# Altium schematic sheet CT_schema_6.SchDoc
size 369 x 245 mm
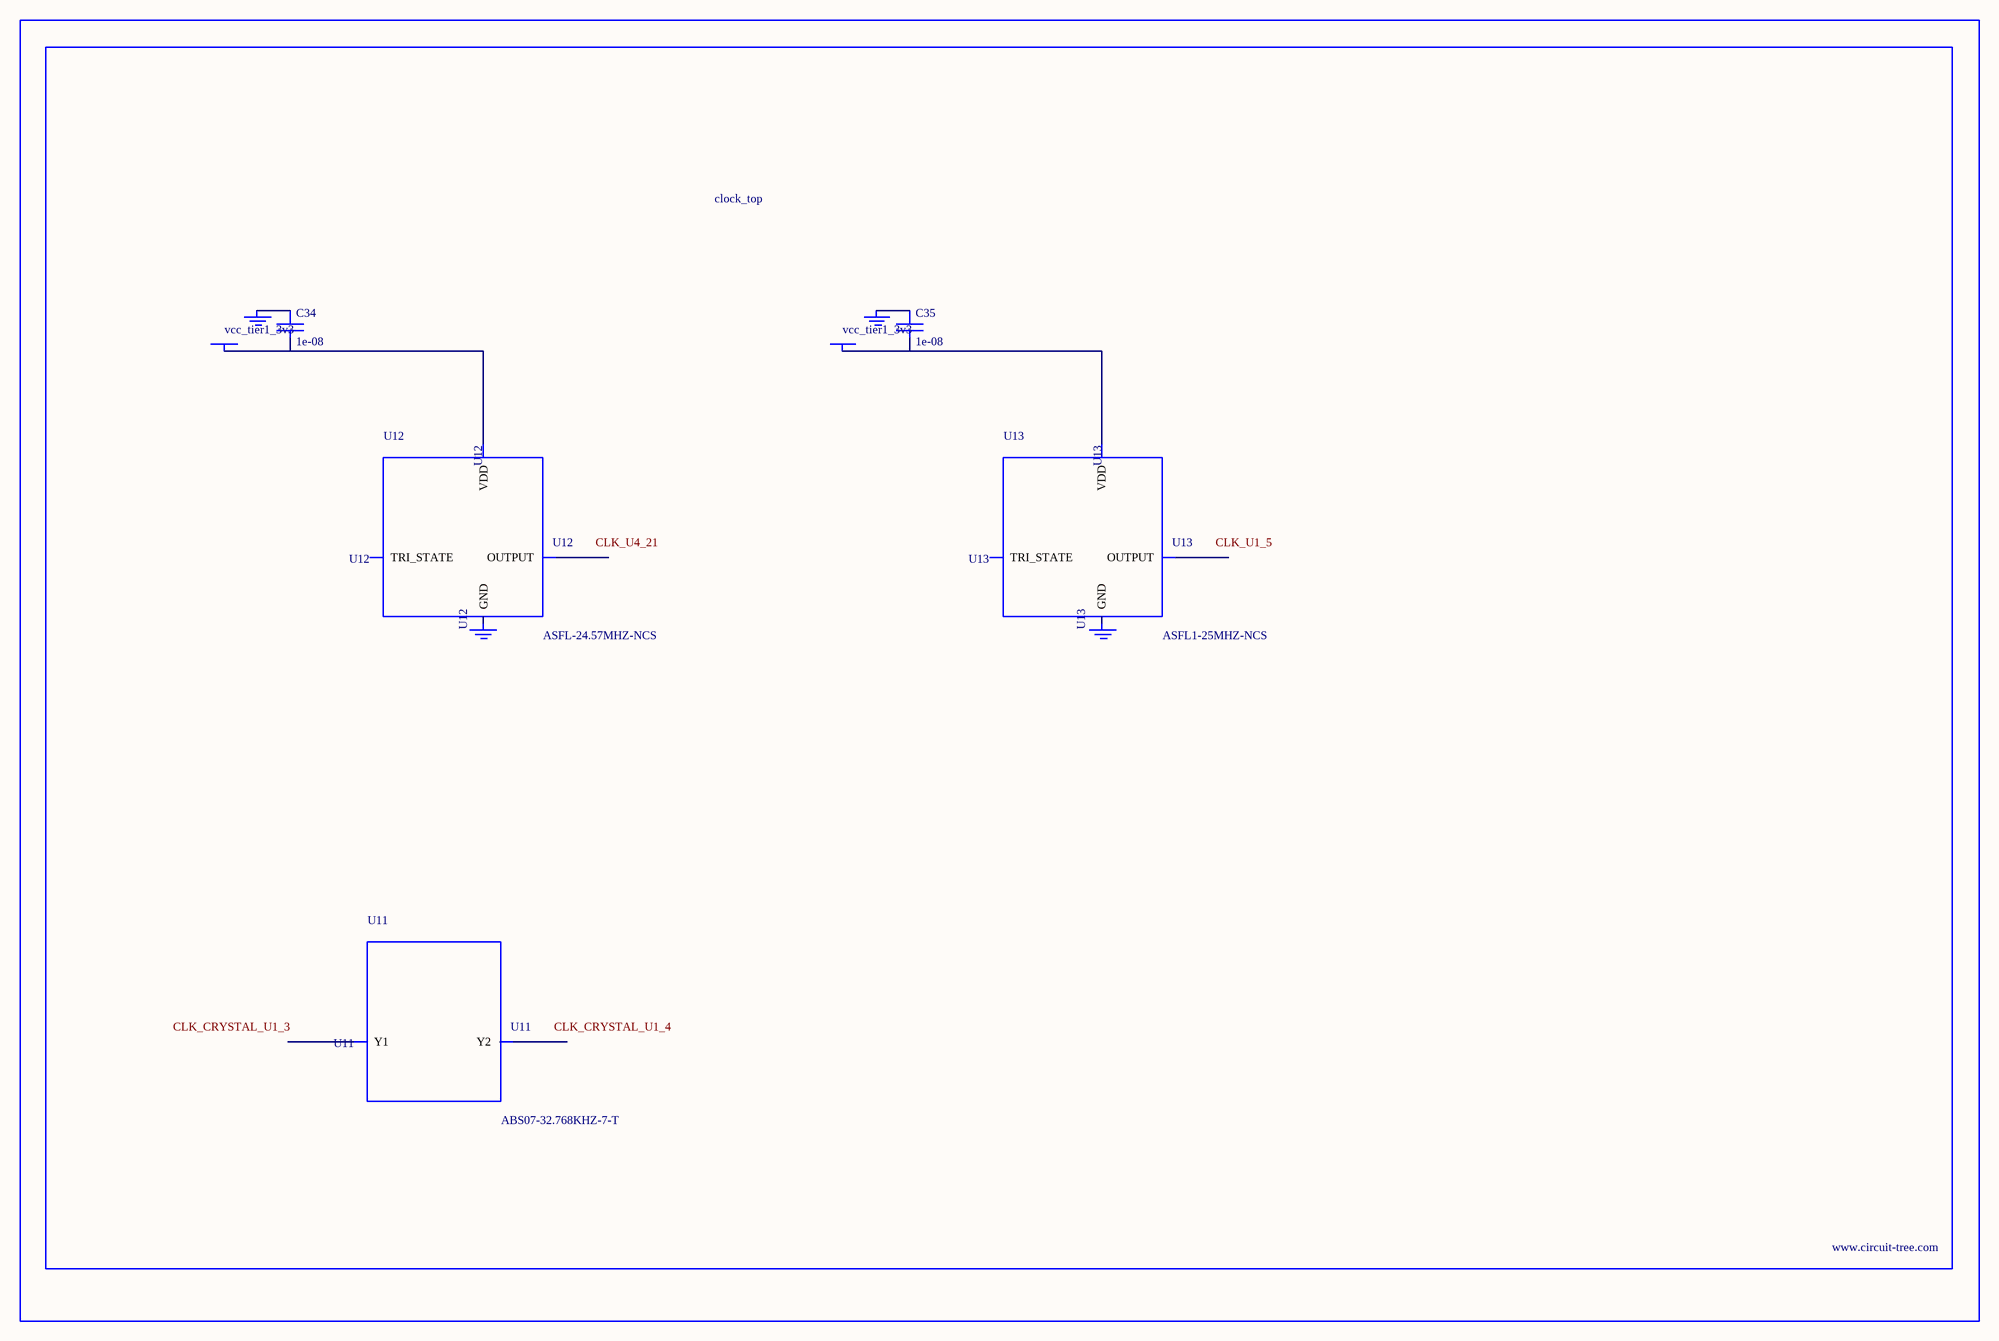
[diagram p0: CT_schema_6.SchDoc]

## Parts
BORDER5  (no value)
C34  1e-08  [C0402]
C35  1e-08  [C0402]
GND_INSTANCE_5_0  (no value)
GND_INSTANCE_5_1  (no value)
GND_INSTANCE_5_2  (no value)
GND_INSTANCE_5_3  (no value)
POWER_INSTANCE_5_0  vcc_tier1_3v3
POWER_INSTANCE_5_1  vcc_tier1_3v3
U11  ABS07-32.768KHZ-7-T  [ABS07-32.768KHZ-7-T]
U12  ASFL-24.57MHZ-NCS  [ASFL1]
U13  ASFL1-25MHZ-NCS  [ASFL1]

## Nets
NetC34_1: C34.1 GND_INSTANCE_5_0.0(GND)
NetC34_2: C34.2 POWER_INSTANCE_5_0.0(PWR) U12.4(VDD)
NetC35_1: C35.1 GND_INSTANCE_5_2.0(GND)
NetC35_2: C35.2 POWER_INSTANCE_5_1.0(PWR) U13.4(VDD)

Not connected (* = marked no-connect by the designer): GND_INSTANCE_5_1 0(GND); GND_INSTANCE_5_3 0(GND); U11 1(Y1) 2(Y2); U12 1(TRI_STATE) 2(GND) 3(OUTPUT); U13 1(TRI_STATE) 2(GND) 3(OUTPUT)

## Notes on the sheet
- Labels drawn without touching a wire or pin: CLK_CRYSTAL_U1_3, CLK_CRYSTAL_U1_4, CLK_U1_5, CLK_U4_21

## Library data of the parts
BORDER5 = BORDER_PAGE5
C34 C35 = C0402C103K3RAC
GND_INSTANCE_5_0-GND_INSTANCE_5_3 = GND
POWER_INSTANCE_5_0 POWER_INSTANCE_5_1 = PWR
